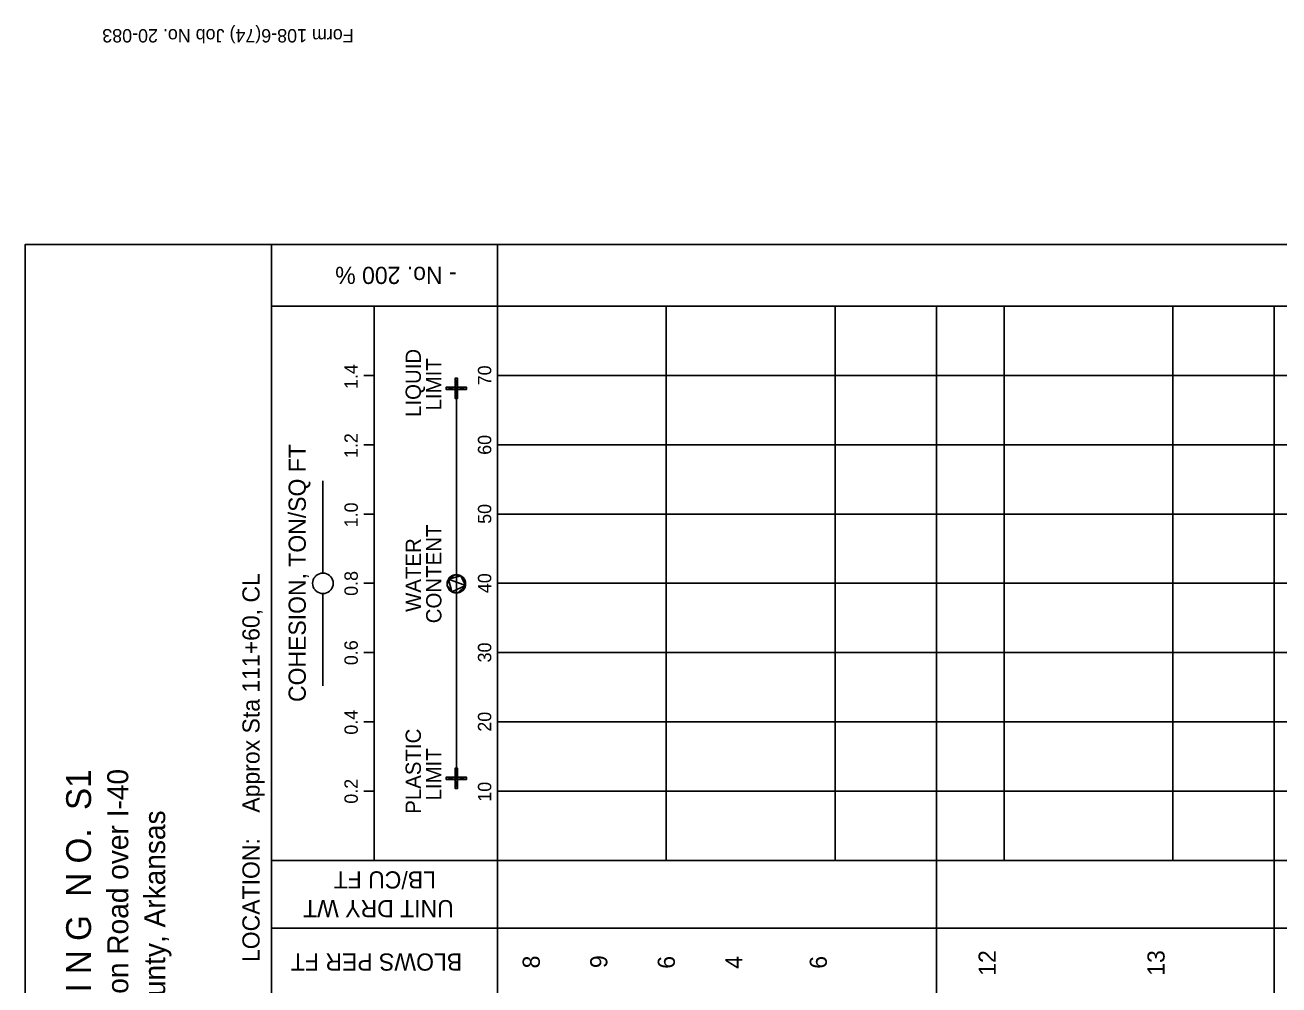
# Model space of a CAD drawing. Extents: x 1313964 to 1316843, y 2087046 to 2096619.
# Drawn here: x 1313975.39 to 1314012.51, y 2089839.64 to 2089868.08 of the extents above; entities that cross this region are included whole.
import ezdxf

# ---------------------------------------------------------------- set-up
doc = ezdxf.new("R2010")
doc.units = 0
doc.layers.add('B-Sub-Contour', color=7, linetype='Continuous')
doc.layers.add('Default', color=7, linetype='Continuous')

# ---------------------------------------------------------------- blocks, each defined once
blk = doc.blocks.new('DMK_7')
at = {"layer": 'Default'}
blk.add_lwpolyline([(0, -15240), (2651.76, -15011.4), (5212.08, -14325.6), (7620, -13197.84), (9799.32, -11673.84), (10774.68, -10774.68), (11673.84, -9799.32), (13197.84, -7620), (14325.6, -5212.08), (15011.4, -2651.76), (15240, 0), (15011.4, 2651.76), (14325.6, 5212.08), (13197.84, 7620), (11673.84, 9799.32), (10774.68, 10774.68), (9799.32, 11673.84), (7620, 13197.84), (5212.08, 14325.6), (2651.76, 15011.4), (0, 15240), (-2651.76, 15011.4), (-5212.08, 14325.6), (-7620, 13197.84), (-9799.32, 11673.84), (-10774.68, 10774.68), (-11673.84, 9799.32), (-13197.84, 7620), (-14325.6, 5212.08), (-15011.4, 2651.76), (-15240, 0), (-15011.4, -2651.76), (-14325.6, -5212.08), (-13197.84, -7620), (-11673.84, -9799.32), (-10774.68, -10774.68), (-9799.32, -11673.84), (-7620, -13197.84), (-5212.08, -14325.6), (-2651.76, -15011.4), (0, -15240)], dxfattribs=at)
blk = doc.blocks.new('DMK_99')
at = {"layer": 'Default'}
for points in [[(-1524, -1524), (-1524, 1524), (-15240, 1524), (-1524, -1524)], [(-1524, -1524), (-15240, 1524), (-15240, -1524), (-1524, -1524)], [(1524, 1524), (1524, 15240), (-1524, 15240), (1524, 1524)], [(1524, 1524), (-1524, 15240), (-1524, 1524), (1524, 1524)], [(-1524, -1524), (1524, -1524), (1524, 1524), (-1524, -1524)], [(-1524, -1524), (1524, 1524), (-1524, 1524), (-1524, -1524)], [(1524, -1524), (15240, -1524), (15240, 1524), (1524, -1524)], [(1524, -1524), (15240, 1524), (1524, 1524), (1524, -1524)], [(-1524, -1524), (-1524, -15240), (1524, -15240), (-1524, -1524)], [(-1524, -1524), (1524, -15240), (1524, -1524), (-1524, -1524)]]:
    blk.add_lwpolyline(points, close=True, dxfattribs=at)
blk = doc.blocks.new('POINT_DISPLAY')
at = {"layer": 'Default'}
blk.add_line((0, 0), (0, 0), dxfattribs=at)
blk = doc.blocks.new('DMK_101')
at = {"layer": 'Default'}
for points in [[(-14269.212, 2386.584), (-14476.476, 0), (-14269.212, -2386.584), (-14269.212, 2386.584)], [(-12638.532, 6858), (-13653.516, 4690.872), (-14269.212, 2386.584), (-12638.532, 6858)], [(-12638.532, 6858), (-14269.212, 2386.584), (-14269.212, -2386.584), (-12638.532, 6858)], [(-12638.532, 6858), (-14269.212, -2386.584), (-3147.06, -13508.736), (-12638.532, 6858)], [(-3147.06, 13511.784), (-7618.476, 11878.056), (-12638.532, 6858), (-3147.06, 13511.784)], [(6097.524, 11878.056), (-3147.06, 13511.784), (-12638.532, 6858), (6097.524, 11878.056)], [(-7618.476, 11878.056), (-11266.932, 8820.912), (-12638.532, 6858), (-7618.476, 11878.056)], [(-3147.06, -13508.736), (6097.524, 11878.056), (-12638.532, 6858), (-3147.06, -13508.736)], [(-7618.476, 11878.056), (-9578.34, 10506.456), (-11266.932, 8820.912), (-7618.476, 11878.056)], [(-9578.34, 10506.456), (-10456.164, 9698.736), (-11266.932, 8820.912), (-9578.34, 10506.456)], [(-3147.06, 13511.784), (-5451.348, 12893.04), (-7618.476, 11878.056), (-3147.06, 13511.784)], [(1626.108, 13511.784), (-760.476, 13712.952), (-3147.06, 13511.784), (1626.108, 13511.784)], [(6097.524, 11878.056), (1626.108, 13511.784), (-3147.06, 13511.784), (6097.524, 11878.056)], [(-3147.06, -13508.736), (11117.58, -6858), (6097.524, 11878.056), (-3147.06, -13508.736)], [(6097.524, 11878.056), (3930.396, 12893.04), (1626.108, 13511.784), (6097.524, 11878.056)], [(11117.58, 6858), (8060.436, 10506.456), (6097.524, 11878.056), (11117.58, 6858)], [(12751.308, 2386.584), (11117.58, 6858), (6097.524, 11878.056), (12751.308, 2386.584)], [(11117.58, -6858), (12751.308, 2386.584), (6097.524, 11878.056), (11117.58, -6858)], [(9745.98, 8820.912), (8938.26, 9698.736), (8060.436, 10506.456), (9745.98, 8820.912)], [(11117.58, 6858), (9745.98, 8820.912), (8060.436, 10506.456), (11117.58, 6858)], [(12751.308, 2386.584), (12132.564, 4690.872), (11117.58, 6858), (12751.308, 2386.584)], [(11117.58, -6858), (12751.308, -2386.584), (12751.308, 2386.584), (11117.58, -6858)], [(12751.308, -2386.584), (12952.476, 0), (12751.308, 2386.584), (12751.308, -2386.584)], [(-14269.212, -2386.584), (-13653.516, -4690.872), (-12638.532, -6858), (-14269.212, -2386.584)], [(-14269.212, -2386.584), (-12638.532, -6858), (-9578.34, -10506.456), (-14269.212, -2386.584)], [(-14269.212, -2386.584), (-9578.34, -10506.456), (-3147.06, -13508.736), (-14269.212, -2386.584)], [(-12638.532, -6858), (-11266.932, -8817.864), (-9578.34, -10506.456), (-12638.532, -6858)], [(-11266.932, -8817.864), (-10456.164, -9695.688), (-9578.34, -10506.456), (-11266.932, -8817.864)], [(-9578.34, -10506.456), (-7618.476, -11878.056), (-3147.06, -13508.736), (-9578.34, -10506.456)], [(-7618.476, -11878.056), (-5451.348, -12893.04), (-3147.06, -13508.736), (-7618.476, -11878.056)], [(-3147.06, -13508.736), (6097.524, -11878.056), (11117.58, -6858), (-3147.06, -13508.736)], [(-3147.06, -13508.736), (1626.108, -13508.736), (6097.524, -11878.056), (-3147.06, -13508.736)], [(-3147.06, -13508.736), (-760.476, -13716), (1626.108, -13508.736), (-3147.06, -13508.736)], [(1626.108, -13508.736), (3930.396, -12893.04), (6097.524, -11878.056), (1626.108, -13508.736)], [(6097.524, -11878.056), (8060.436, -10506.456), (11117.58, -6858), (6097.524, -11878.056)], [(8060.436, -10506.456), (9745.98, -8817.864), (11117.58, -6858), (8060.436, -10506.456)], [(8060.436, -10506.456), (8938.26, -9695.688), (9745.98, -8817.864), (8060.436, -10506.456)], [(11117.58, -6858), (12132.564, -4690.872), (12751.308, -2386.584), (11117.58, -6858)]]:
    blk.add_lwpolyline(points, close=True, dxfattribs=at)
blk.add_blockref('POINT_DISPLAY', (14479.524, 0), dxfattribs=at)

msp = doc.modelspace()

# ---------------------------------------------------------------- linework, layer by layer
at = {"layer": 'B-Sub-Contour'}
for points in [[(1314036.804, 2089818.705), (1314036.804, 2089861.576), (1313975.385, 2089861.576), (1313975.385, 2089818.705), (1314036.804, 2089818.705)], [(1313982.683, 2089818.705), (1313982.683, 2089861.576)], [(1313989.372, 2089818.705), (1313989.372, 2089861.576)], [(1314034.372, 2089859.752), (1313982.683, 2089859.752)], [(1313985.723, 2089859.752), (1313985.419, 2089859.752)], [(1313985.723, 2089843.333), (1313985.723, 2089859.752)], [(1314034.372, 2089859.752), (1313989.372, 2089859.752)], [(1313989.372, 2089843.333), (1313989.372, 2089859.752)], [(1313994.372, 2089843.333), (1313994.372, 2089859.752)], [(1313999.372, 2089843.333), (1313999.372, 2089859.752)], [(1314002.372, 2089839.319), (1314002.372, 2089859.752)], [(1314004.372, 2089843.333), (1314004.372, 2089859.752)], [(1314009.372, 2089843.333), (1314009.372, 2089859.752)], [(1314012.372, 2089839.319), (1314012.372, 2089859.752)], [(1313985.723, 2089857.7), (1313985.419, 2089857.7)], [(1314034.372, 2089857.7), (1313989.372, 2089857.7)], [(1313988.155, 2089845.765), (1313988.155, 2089857.319)], [(1313985.723, 2089855.647), (1313985.419, 2089855.647)], [(1314034.372, 2089855.647), (1313989.372, 2089855.647)], [(1313984.203, 2089851.846), (1313984.203, 2089854.583)], [(1313985.723, 2089853.595), (1313985.419, 2089853.595)], [(1314034.372, 2089853.595), (1313989.372, 2089853.595)], [(1313985.723, 2089851.542), (1313985.419, 2089851.542)], [(1314034.372, 2089851.542), (1313989.372, 2089851.542)], [(1313984.203, 2089848.502), (1313984.203, 2089851.238)], [(1313985.723, 2089849.49), (1313985.419, 2089849.49)], [(1314034.372, 2089849.49), (1313989.372, 2089849.49)], [(1313985.723, 2089847.438), (1313985.419, 2089847.438)], [(1314034.372, 2089847.438), (1313989.372, 2089847.438)], [(1313985.723, 2089845.385), (1313985.419, 2089845.385)], [(1314034.372, 2089845.385), (1313989.372, 2089845.385)], [(1314034.372, 2089843.333), (1313982.683, 2089843.333)], [(1313985.723, 2089843.333), (1313985.419, 2089843.333)], [(1314034.372, 2089843.333), (1313989.372, 2089843.333)], [(1314034.372, 2089841.326), (1313982.683, 2089841.326)]]:
    msp.add_lwpolyline(points, dxfattribs=at)

# ---------------------------------------------------------------- block references
at = {"layer": 'B-Sub-Contour', "xscale": 1.9951013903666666e-05, "yscale": 1.9951013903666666e-05, "rotation": 90}
for name, p in [('DMK_99', (1313988.155, 2089857.319)), ('DMK_7', (1313984.203, 2089851.542)), ('DMK_101', (1313988.155, 2089851.542)), ('DMK_99', (1313988.155, 2089845.765))]:
    msp.add_blockref(name, p, dxfattribs=at)

# ---------------------------------------------------------------- texts
at = {"layer": 'B-Sub-Contour'}
for s, height, rotation, p in [('Form 108-6(74) Job No. 20-083', 0.39588, 180, (1313985.115, 2089867.961)), ('- No. 200 %', 0.50899, 180, (1313988.163, 2089860.919)), ('LIQUID', 0.4524, 90, (1313987.105, 2089856.471)), ('LIMIT', 0.4524, 90, (1313987.713, 2089856.664)), ('1.4', 0.3959, 90, (1313985.237, 2089857.298)), ('70', 0.3959, 90, (1313989.189, 2089857.408)), ('1.2', 0.3959, 90, (1313985.237, 2089855.253)), ('60', 0.3959, 90, (1313989.189, 2089855.349)), ('COHESION, TON/SQ FT', 0.50899, 90, (1313983.697, 2089848.026)), ('1.0', 0.3959, 90, (1313985.237, 2089853.201)), ('50', 0.3959, 90, (1313989.189, 2089853.304)), ('CONTENT', 0.4524, 90, (1313987.713, 2089850.358)), ('WATER', 0.4524, 90, (1313987.105, 2089850.694)), ('LOCATION:    Approx Sta 111+60, CL', 0.50899, 90, (1313982.329, 2089840.323)), ('0.8', 0.3959, 90, (1313985.237, 2089851.171)), ('40', 0.3959, 90, (1313989.189, 2089851.251)), ('0.6', 0.3959, 90, (1313985.237, 2089849.118)), ('30', 0.3959, 90, (1313989.189, 2089849.199)), ('0.4', 0.3959, 90, (1313985.237, 2089847.058)), ('20', 0.3959, 90, (1313989.189, 2089847.147)), ('PLASTIC', 0.4524, 90, (1313987.105, 2089844.715)), ('LIMIT', 0.4524, 90, (1313987.713, 2089845.11)), ('L O G  O F  B O R I N G  N O.  S1', 0.7352, 90, (1313977.337, 2089831.115)), ('061610 - Remington Road over I-40', 0.62209, 90, (1313978.44, 2089832.77)), ('0.2', 0.3959, 90, (1313985.237, 2089845.013)), ('10', 0.3959, 90, (1313989.189, 2089845.072)), ('Lonoke County, Arkansas', 0.62209, 90, (1313979.534, 2089835.288)), ('LB/CU FT', 0.509, 180, (1313987.549, 2089843.01)), ('UNIT DRY WT', 0.50899, 180, (1313988.078, 2089842.158)), ('BLOWS PER FT', 0.50899, 180, (1313988.324, 2089840.577)), ('8', 0.509, 90, (1313990.626, 2089840.134)), ('9', 0.509, 90, (1313992.626, 2089840.143)), ('6', 0.509, 90, (1313994.626, 2089840.124)), ('4', 0.509, 90, (1313996.626, 2089840.124)), ('6', 0.509, 90, (1313999.126, 2089840.124)), ('12', 0.509, 90, (1314004.126, 2089839.916)), ('13', 0.509, 90, (1314009.126, 2089839.916))]:
    msp.add_text(s, height=height, rotation=rotation, dxfattribs=at).set_placement(p)

doc.saveas('drawing.dxf')
